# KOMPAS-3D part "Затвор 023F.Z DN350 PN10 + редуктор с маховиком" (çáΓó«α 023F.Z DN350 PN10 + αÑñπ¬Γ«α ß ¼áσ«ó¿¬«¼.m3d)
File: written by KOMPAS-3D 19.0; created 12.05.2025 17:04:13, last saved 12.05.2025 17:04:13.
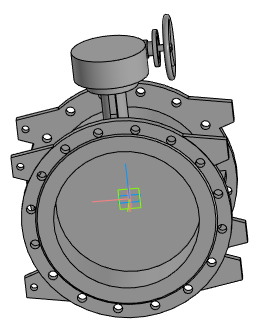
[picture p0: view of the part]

Document properties: Полное имя файла: Затвор 023F.Z DN350 PN10 + редуктор с маховиком.a3d

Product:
- Part/product: Затвор 023F.Z DN350 PN10 + редуктор с маховиком
    Масса: 128.58

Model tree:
1. Операция без истории:1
